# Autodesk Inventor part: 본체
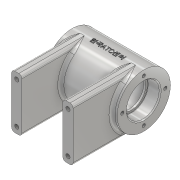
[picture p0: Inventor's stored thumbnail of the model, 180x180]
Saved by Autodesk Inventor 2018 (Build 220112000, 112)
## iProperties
Created: 2020-07
Part Number: 본체
Material: 알루미늄 6061-AHC
Document SubType Name: Modeling
Designer: Administrator
Density: 2.7 g/cm^3
Appearance: 알루미늄 - 짙음
Mass: 305.294 g
Surface Area: 357.55 cm^2
Volume: 113.072 cm^3
Author: Administrator
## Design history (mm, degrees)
sketch "스케치1"
  geometry: L1 (35, 26)-(-35, 26); L2 (-35, 26)-(-35, 16); L3 (-35, 0)-(35, 0); L4 (35, 26)-(35, 16); L5 (35, 16)-(23, 16); L6 (23, 16)-(23, 14); L7 (23, 14)-(21, 14); L8 (21, 14)-(21, 21); L9 (21, 21)-(-21, 21); L10 (-21, 21)-(-21, 14); L11 (-21, 14)-(-23, 14); L12 (-23, 14)-(-23, 16); L13 (-23, 16)-(-35, 16); 1 further point
  constraints: 26 end point, 5 perpendicular, 4 horizontal, 2 parallel, 2 vertical
  dimensions: "d1" = 26 distance of L3.end L1.start; "d2" = 70 distance of L1.start L1.end; "d3" = 16 distance of L3.end L4.end; "d7" = 2 distance of L7.end L6.end; "d9" = 42 distance of L8.end L9.end; "d10" = 7 distance of L9.end L10.end; "d11" = 2 distance of L10.end L11.end; "d12" = 2 distance of L11.end L12.end; "d13" = 7 distance of L7.end L8.end; "d14" = 12 distance between parallel lines of L6 L4; "d15" = 2 distance between parallel lines of L5 L7; "d16" = 10 distance between parallel lines of L5 L1; "d17" = 35 distance from line of point (0, 0) L4; "d18" = 16 distance from line of point (0, 0) L5; "d19" = 70 distance from line of L3.start L4
revolve "회전1" sketch "스케치1" stored, may be unused: angle "d20" = 90 deg
chamfer "모따기1" distance "d21" = 1; stored, may be unused: second distance "d22" = 2, angle "d23" = 45 deg
fillet "모깎기1" dims "d24" = 3
fillet "모깎기2" dims "d25" = 0.3
sketch "스케치2"
  geometry: A1 r 21 centre (0, 0) between (0, 21) and (0, -21); A2 r 21 centre (0, 0) between (0, 21) and (-21, 0) reference; 2 further points
  constraints: 4 point on circle, 1 centre point, 1 coincident
  dimensions: "d26" = 42 diameter of A1
hole "구멍1" sketch "스케치2" at (0, 21), (-21, 0), (0, -21), (21, 0) diameter "d27" = 3.242; stored, may be unused: countersink angle "d31" = 90 deg, drill point angle "d33" = 118 deg; dims "d28" = 8, "d29" = 4, "d30" = 2, "d32" = 10
node "작업 평면1"
sketch "스케치3"
  geometry: C1 r 5 at (0, 0); 1 further point
  constraints: 1 centre point, 1 coincident
  dimensions: "d35" = 10 diameter of C1
extrude "돌출1" join sketch "스케치3" stored distance "d36" = 10; taper "d37" = 0 deg
sketch "스케치4"
  geometry: 2 further points
  constraints: 1 coincident
hole "구멍2" sketch "스케치4" at (0, 0) diameter "d38" = 4.917; stored, may be unused: countersink angle "d42" = 90 deg, drill point angle "d44" = 118 deg; dims "d39" = 20, "d40" = 4, "d41" = 2, "d43" = 20
fillet "모깎기4" dims "d60" = 2
node "작업 평면2"
sketch "스케치7"
  geometry: L1 (0, 0)-(30, 0); L2 (30, 0)-(30, 26); L3 (30, 0)-(30, -26); L4 (30, -26)-(20, -26); L5 (35, -26)-(-35, -26) reference; L6 (20, -26)-(20, 26); L7 (20, 26)-(30, 26)
  constraints: 12 end point, 3 vertical, 1 horizontal, 1 point on line
  dimensions: "d62" = 30 distance of L1.start L1.end; "d63" = 26 distance of L1.end L2.end; "d66" = 26 distance of L1.end L3.end; "d67" = 10 distance of L3.end L4.end; "d69" = 52 distance of L4.end L6.end
extrude "돌출2" join sketch "스케치7" stored distance "d70" = 26 (= d66); taper "d71" = 0 deg
fillet "모깎기5" dims "d72" = 3
fillet "모깎기6" dims "d73" = 3
sketch "스케치8"
  geometry: L1 (0, 0)-(0, 20); L2 (0, 20)-(-64.656, 20); L3 (-25, 19.379)-(-35, 19.379) reference; L4 (-27, 26)-(-23, 26) reference; L5 (-25, 26)-(-25, 11.9); L6 (-25, 22.621)-(-25, 19.379) reference; C1 r 2.458 at (0, 0) reference; 2 further points
  constraints: 6 end point, 2 point on line, 2 vertical, 1 midpoint, 1 parallel
  dimensions: "d74" = 20 distance of L1.start L1.end
hole "구멍4" sketch "스케치8" at (-25, 20) diameter "d75" = 4.134; stored, may be unused: countersink angle "d79" = 90 deg, drill point angle "d81" = 118 deg; dims "d76" = 8, "d77" = 4, "d78" = 2, "d80" = 10
sketch "스케치10"
  geometry: L1 (0, 0)-(-27.251, -9.919); L2 (-27.251, -9.919)-(-25.199, -15.557); L3 (-25.199, -15.557)-(-19.222, -13.381); L4 (-19.222, -13.381)-(-21.274, -7.743); L5 (-21.274, -7.743)-(-27.251, -9.919); A1 r 29 centre (0, 0) between (-17.664, 23) and (-17.664, -23) reference
  constraints: 10 end point, 1 perpendicular, 1 point on line, 1 tangent
  dimensions: "d87" = 29 distance of L1.start L1.end; "d89" = 12 diameter of L2.end L1
revolve "회전3" sketch "스케치10" stored, may be unused: angle "d90" = 90 deg
sketch "스케치11"
  geometry: 2 further points
  constraints: 1 coincident
hole "구멍5" sketch "스케치11" at (0, 0) diameter "d91" = 5.188; stored, may be unused: countersink angle "d95" = 90 deg, drill point angle "d97" = 118 deg; dims "d92" = 20, "d93" = 4, "d94" = 2, "d96" = 16
fillet "모깎기7" dims "d98" = 2
node "작업 평면4"
sketch "스케치12"
  geometry: L1 (-35, -26)-(-35, 26) reference; L2 (-35, 26)-(35, 26) reference; 2 further points
  constraints: 1 other
  dimensions: "d99" = 35 distance from line of L1 point (0, 0); "d100" = 26 distance from line of L2 point (0, 0)
feature "엠보싱2" sketch "스케치12" dims "d101" = 0.5, "d102" = 0
node "솔리드1"
mirror "미러1"
mirror "미러2"
mirror "미러3"
mirror "미러4"
other parameters: "d34" = 29, "d61" = -64
